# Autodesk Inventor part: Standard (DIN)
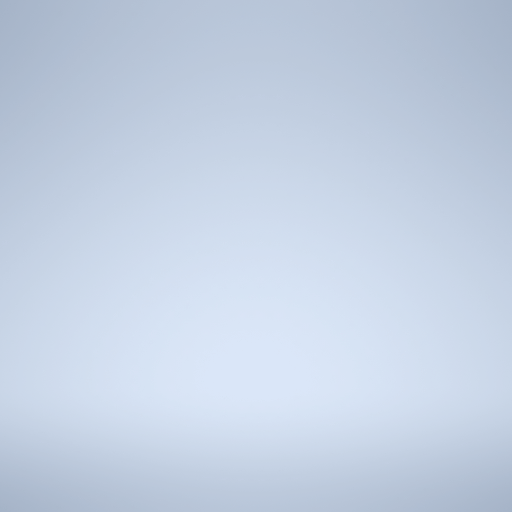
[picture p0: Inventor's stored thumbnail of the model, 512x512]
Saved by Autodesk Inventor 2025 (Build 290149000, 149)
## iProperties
Shininess: 64.0
Length Units: 11269
Angle Units: 11279
Time Units: 11290
Mass Units: 11283
Length Display Precision: 3
Angle Display Precision: 2
Compacted: True
Part Number: Standard (DIN)
Document SubType Name: Modeling
Created: 2002-07
Density: 1 g/cm^3
Material: Všeobecné
Appearance: Výchozí
Density: 0.0
Volumn: 0.0
Area: 0.0
PropertySet Name: Model Information
Control State: 0
Master: False
Checked Out: False
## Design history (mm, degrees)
